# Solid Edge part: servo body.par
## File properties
Last saved by: nakano
Revision: 75
Density: 1473.53664352308 kg/m^3
Accuracy: 0.990
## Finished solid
Body 1: solid body, 149 faces, 376 edges, 232 vertices.
  Faces by surface: plane 91, cylinder 49, torus 9
  Edges by curve: line 257, circle 103, ellipse 16
Bounding box of the edges (mm; curved faces can reach further): 52.832 x 37.516 x 19.685, from (-26.543, -4.1402, -9.8425) to (26.289, 33.3756, 9.8425).
Cylindrical faces by radius (mm): R0.0023 x4, R0.254 x4, R0.381 x4, R0.508 x4, R0.762 x8, R0.889 x4, R1.1176 x4, R1.651 x4, R1.778 x4, R2.1844 x4, R2.794 x1, R5.461 x1, R5.6643 x1, R6.4516 x1, R9.398 x1
Toroidal faces (ring radius, tube radius in mm): R0.508 r0.381 x4, R0.6604 r1.016 x4, R6.0706 r0.381 x1
Planar faces by outward normal: +x 9, +y 14, +z 16, -x 11, -y 17, -z 16, oblique 8
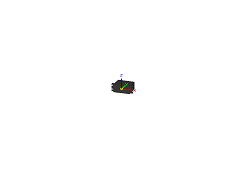
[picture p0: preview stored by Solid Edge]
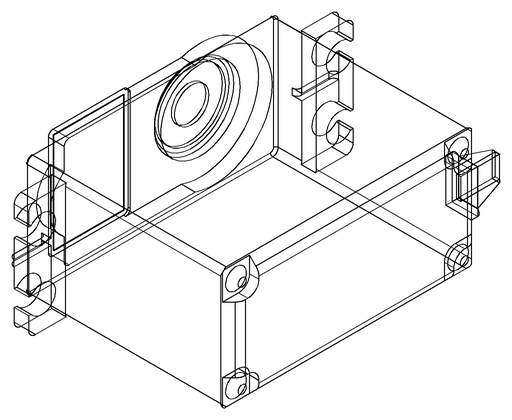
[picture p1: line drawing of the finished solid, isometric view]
